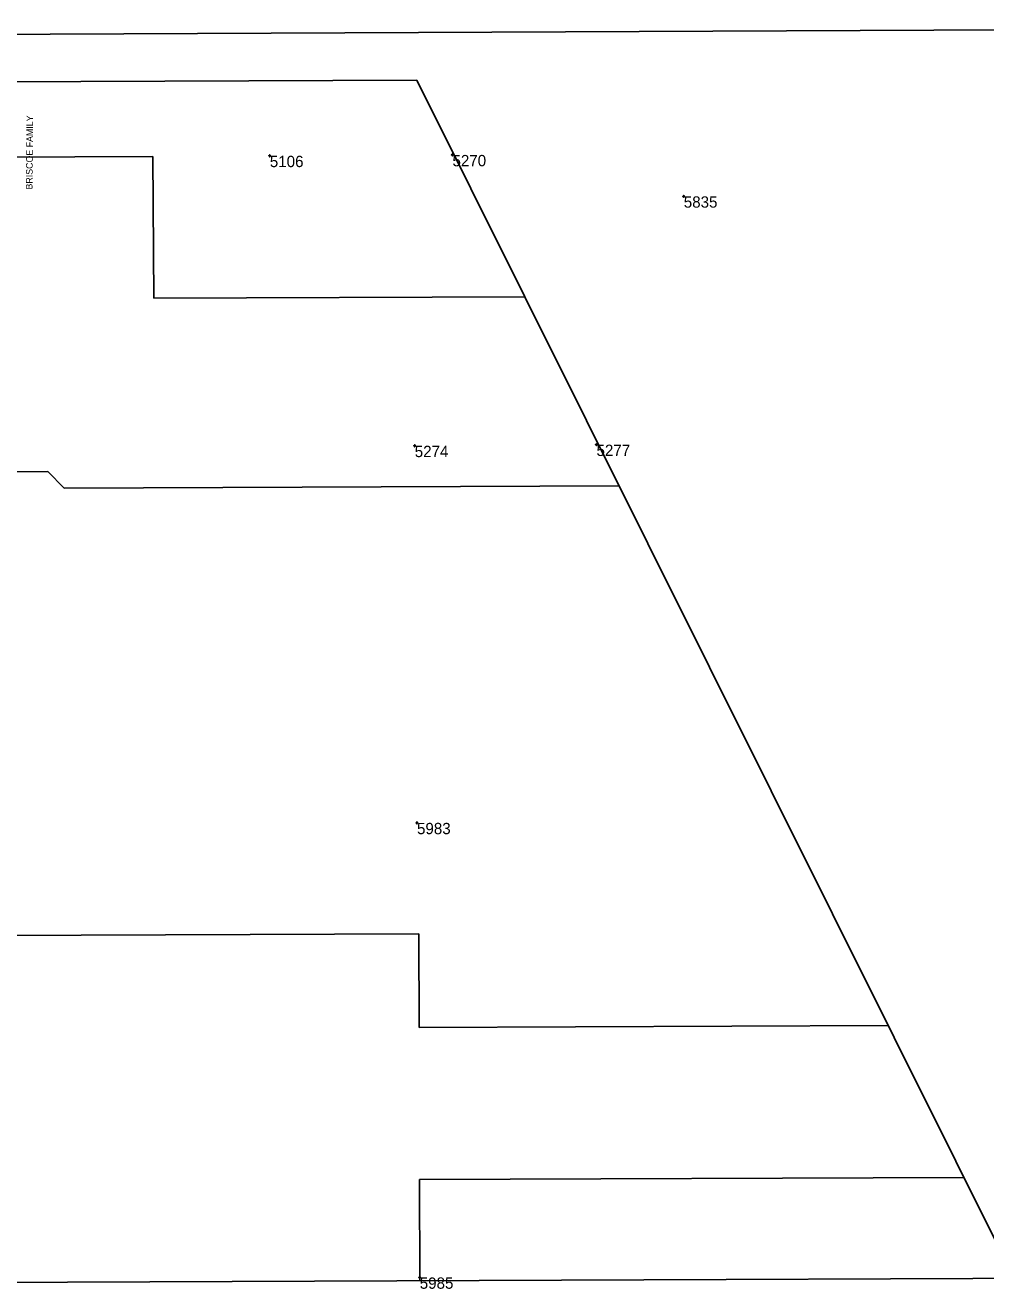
# Model space of a CAD drawing. Extents: x 2145146 to 2158053, y 137507 to 150829.
# Drawn here: x 2151410 to 2152428, y 146965 to 148297 of the extents above; entities that cross this region are included whole.
import ezdxf

# ---------------------------------------------------------------- set-up
doc = ezdxf.new("R2010")
doc.units = 0
for name, color, linetype in [('ALIGN_Cogo Points', 7, 'Continuous'), ('ALIGN_ROW Line', 7, 'Continuous'), ('PLSS_Block Line', 7, 'Continuous'), ('PLSS_Property Line', 7, 'Continuous'), ('PLSS_Section Line', 7, 'Continuous'), ('PLSS_Text_TURNED OFF', 7, 'Continuous')]:
    doc.layers.add(name, color=color, linetype=linetype)

msp = doc.modelspace()

# ---------------------------------------------------------------- linework, layer by layer
at = {"layer": 'ALIGN_Cogo Points'}
for points in [[(2151669.4, 148158.2), (2151669.4, 148159.4), (2151669.4, 148158.2), (2151668.2, 148158.2), (2151669.4, 148158.2), (2151669.4, 148157), (2151669.4, 148158.2), (2151670.6, 148158.2)], [(2151863, 148159.1), (2151863, 148160.3), (2151863, 148159.1), (2151861.8, 148159.1), (2151863, 148159.1), (2151863, 148157.9), (2151863, 148159.1), (2151864.2, 148159.1)], [(2152108.2, 148115.2), (2152108.2, 148116.4), (2152108.2, 148115.2), (2152107, 148115.2), (2152108.2, 148115.2), (2152108.2, 148114), (2152108.2, 148115.2), (2152109.4, 148115.2)], [(2151823, 147850.6), (2151823, 147851.8), (2151823, 147850.6), (2151821.8, 147850.6), (2151823, 147850.6), (2151823, 147849.4), (2151823, 147850.6), (2151824.2, 147850.6)], [(2152015.7, 147851.8), (2152015.7, 147853), (2152015.7, 147851.8), (2152014.5, 147851.8), (2152015.7, 147851.8), (2152015.7, 147850.6), (2152015.7, 147851.8), (2152016.9, 147851.8)], [(2151825.4, 147450.6), (2151825.4, 147451.8), (2151825.4, 147450.6), (2151824.2, 147450.6), (2151825.4, 147450.6), (2151825.4, 147449.4), (2151825.4, 147450.6), (2151826.6, 147450.6)], [(2151828.3, 146968.4), (2151828.3, 146969.6), (2151828.3, 146968.4), (2151827.1, 146968.4), (2151828.3, 146968.4), (2151828.3, 146967.2), (2151828.3, 146968.4), (2151829.5, 146968.4)]]:
    msp.add_lwpolyline(points, dxfattribs=at)
at = {"layer": 'ALIGN_ROW Line'}
msp.add_line((2151339.3, 148236.5), (2151825.2, 148238.5), dxfattribs=at)
msp.add_lwpolyline([(2153114.2, 145651.7), (2151939.7, 148008.6)], dxfattribs=at)
at = {"layer": 'PLSS_Block Line'}
msp.add_lwpolyline([(2150931, 146961.3), (2153549.3, 146971.8)], dxfattribs=at)
at = {"layer": 'PLSS_Property Line'}
for p, q in [((2151939.7, 148008.6), (2151825.2, 148238.5)), ((2151339.4, 148156.5), (2151545.4, 148157.4)), ((2151545.4, 148157.4), (2151546.3, 148007.1)), ((2151546.3, 148007.1), (2151939.7, 148008.6)), ((2151434, 147823.2), (2151249.7, 147822.4)), ((2151451.4, 147805.7), (2151434, 147823.2)), ((2152039.7, 147808.1), (2151451.4, 147805.7)), ((2151373.8, 147331.1), (2151827.5, 147332.9)), ((2151827.5, 147332.9), (2151827.8, 147233.6)), ((2151827.8, 147233.6), (2152325, 147235.6)), ((2152405.2, 147074.5), (2151828.2, 147072.3)), ((2151828.2, 147072.3), (2151828.5, 146964.9))]:
    msp.add_line(p, q, dxfattribs=at)
at = {"layer": 'PLSS_Section Line'}
msp.add_lwpolyline([(2150890, 148284.8), (2153544, 148296.8)], dxfattribs=at)

# ---------------------------------------------------------------- texts
at = {"layer": 'ALIGN_Cogo Points'}
for s, p in [('5106', (2151669.4, 148146.2)), ('5270', (2151863, 148147.1)), ('5835', (2152108.2, 148103.2)), ('5274', (2151823, 147838.6)), ('5277', (2152015.7, 147839.8)), ('5983', (2151825.4, 147438.6)), ('5985', (2151828.3, 146956.4))]:
    msp.add_text(s, height=12, dxfattribs=at).set_placement(p)
at = {"layer": 'PLSS_Text_TURNED OFF'}
msp.add_text('BRISCOE FAMILY', height=7, rotation=89.4808, dxfattribs=at).set_placement((2151417.8, 148122.4))

doc.saveas('drawing.dxf')
